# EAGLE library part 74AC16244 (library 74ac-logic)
16-bit BUFFER/LINE DRIVER, 3-state
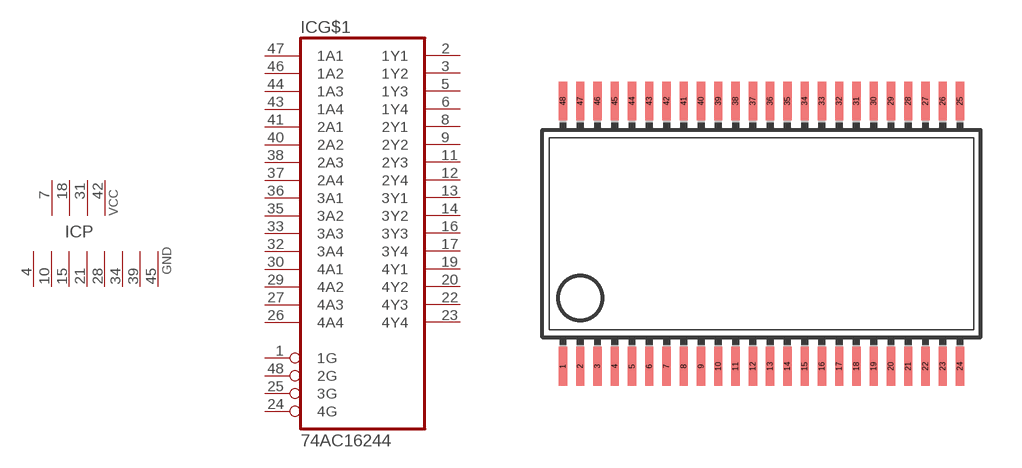
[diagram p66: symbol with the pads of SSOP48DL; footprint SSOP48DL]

Designator prefix IC; gates G$1=7416244 P=4PWR8GND

## 74AC16244  [SSOP48DL]
1  G$1:1G  in
2  G$1:1Y1  hiz
3  G$1:1Y2  hiz
4  P:GND  pwr
5  G$1:1Y3  hiz
6  G$1:1Y4  hiz
7  P:VCC  pwr
8  G$1:2Y1  hiz
9  G$1:2Y2  hiz
10  P:GND  pwr
11  G$1:2Y3  hiz
12  G$1:2Y4  hiz
13  G$1:3Y1  hiz
14  G$1:3Y2  hiz
15  P:GND  pwr
16  G$1:3Y3  hiz
17  G$1:3Y4  hiz
18  P:VCC  pwr
19  G$1:4Y1  hiz
20  G$1:4Y2  hiz
21  P:GND  pwr
22  G$1:4Y3  hiz
23  G$1:4Y4  hiz
24  G$1:4G  in
25  G$1:3G  in
26  G$1:4A4  in
27  G$1:4A3  in
28  P:GND  pwr
29  G$1:4A2  in
30  G$1:4A1  in
31  P:VCC  pwr
32  G$1:3A4  in
33  G$1:3A3  in
34  P:GND  pwr
35  G$1:3A2  in
36  G$1:3A1  in
37  G$1:2A4  in
38  G$1:2A3  in
39  P:GND  pwr
40  G$1:2A2  in
41  G$1:2A1  in
42  P:VCC  pwr
43  G$1:1A4  in
44  G$1:1A3  in
45  P:GND  pwr
46  G$1:1A2  in
47  G$1:1A1  in
48  G$1:2G  in

## Footprint SSOP48DL (pad centres in mm)
Shrink Small Outline Package
smd 0.305 x 1.422: 1 -6.985,-4.877; 2 -6.35,-4.877; 3 -5.715,-4.877; 4 -5.08,-4.877; 5 -4.445,-4.877; 6 -3.81,-4.877; 7 -3.175,-4.877; 8 -2.54,-4.877; 9 -1.905,-4.877; 10 -1.27,-4.877; 11 -0.635,-4.877; 12 0,-4.877; 13 0.635,-4.877; 14 1.27,-4.877; 15 1.905,-4.877; 16 2.54,-4.877; 17 3.175,-4.877; 18 3.81,-4.877; 19 4.445,-4.877; 20 5.08,-4.877; 21 5.715,-4.877; 22 6.35,-4.877; 23 6.985,-4.877; 24 7.62,-4.877; 25 7.62,4.877; 26 6.985,4.877; 27 6.35,4.877; 28 5.715,4.877; 29 5.08,4.877; 30 4.445,4.877; 31 3.81,4.877; 32 3.175,4.877; 33 2.54,4.877; 34 1.905,4.877; 35 1.27,4.877; 36 0.635,4.877; 37 0,4.877; 38 -0.635,4.877; 39 -1.27,4.877; 40 -1.905,4.877; 41 -2.54,4.877; 42 -3.175,4.877; 43 -3.81,4.877; 44 -4.445,4.877; 45 -5.08,4.877; 46 -5.715,4.877; 47 -6.35,4.877; 48 -6.985,4.877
